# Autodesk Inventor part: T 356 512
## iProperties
_DisabledCommands: 0
Created: 2005-12
Part Number: T 356 512
Material: 1.4301
Description: Gewindestange
Vendor: Autodesk Inc.
Document SubType Name: Modeling
Standard: DIN 671
Designer: I.Baliuc
Size Designation: 8 - 130
Density: 7.86 g/cm^3
Zweck: DC - Schalter
Abmessung: Rd 8 - 130
Author: T.Messerschmitt
Keywords: 266137
Revision Number: 356512
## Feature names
1. Körper [Extrusion]
2. Fase1 [Chamfer]
